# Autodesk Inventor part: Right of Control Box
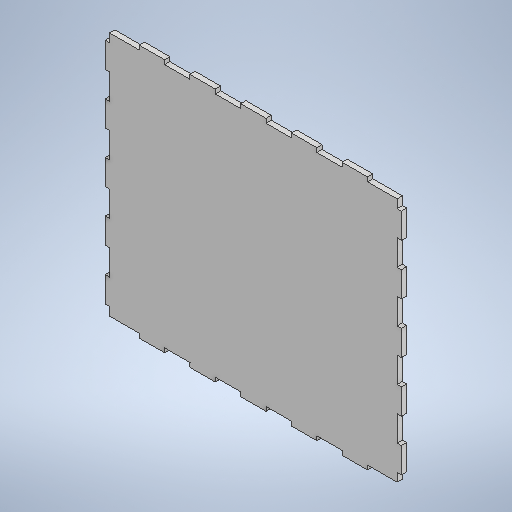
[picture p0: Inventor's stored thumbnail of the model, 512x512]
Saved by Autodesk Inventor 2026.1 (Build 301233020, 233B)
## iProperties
Created: 2026-11
Part Number: Right of Control Box
Material: Generic
Document SubType Name: Modeling
Designer: hp
Density: 1 g/cm^3
Appearance: Default
Author: hp
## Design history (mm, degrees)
sketch "Sketch1"
  geometry: L1 (104, 4)-(104, 0); L2 (104, 4)-(104, 0); L3 (104, 0)-(80, 0); L4 (80, 0)-(80, 4); L5 (104, 0)-(80, 0); L6 (80, 0)-(80, 4); L7 (80, 4)-(104, 4); L8 (80, 4)-(104, 4); L9 (128, 0)-(128, 4); L10 (128, 0)-(128, 4); L11 (152, 0)-(128, 0); L12 (128, 4)-(152, 4); L13 (152, 0)-(128, 0); L14 (128, 4)-(152, 4); L15 (152, 4)-(152, 0); L16 (0, 240)-(280, 240); L17 (280, 240)-(280, 0); L18 (280, 0)-(0, 0); L19 (0, 0)-(0, 240); L20 (56, 4)-(56, 0); L21 (56, 0)-(32, 0); L22 (32, 0)-(32, 4); L23 (32, 4)-(56, 4); L24 (140, 240)-(140, 0); L25 (280, 120)-(0, 120); L26 (176, 0)-(176, 4); L27 (176, 0)-(176, 4); L28 (200, 0)-(176, 0); L29 (200, 0)-(176, 0); L30 (176, 4)-(200, 4); L31 (200, 4)-(200, 0); L32 (224, 0)-(224, 4); L33 (248, 4)-(248, 0); L34 (224, 4)-(248, 4); L35 (248, 0)-(224, 0); L36 (152, 4)-(152, 0); L37 (128, 240)-(128, 236); L38 (128, 240)-(128, 236); L39 (128, 240)-(128, 236); L40 (128, 236)-(152, 236); L41 (128, 236)-(152, 236); L42 (152, 240)-(128, 240); L43 (152, 240)-(128, 240); L44 (152, 236)-(152, 240); L45 (152, 236)-(152, 240); L46 (200, 236)-(200, 240); L47 (176, 240)-(176, 236); L48 (176, 240)-(176, 236); L49 (200, 240)-(176, 240); L50 (176, 236)-(200, 236); L51 (200, 240)-(176, 240); L52 (176, 236)-(200, 236); L53 (200, 236)-(200, 240); L54 (224, 240)-(224, 236); L55 (224, 236)-(248, 236); L56 (248, 240)-(224, 240); L57 (248, 236)-(248, 240); L58 (176, 4)-(200, 4); L59 (200, 4)-(200, 0); L60 (152, 4)-(152, 0); L61 (128, 0)-(128, 4); L62 (152, 0)-(128, 0); L63 (128, 4)-(152, 4); L64 (80, 240)-(80, 236)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; 113 further points
  constraints: 308 end point, 90 symmetric about line, 8 parallel, 6 midpoint, 5 horizontal, 4 perpendicular, 2 vertical, 1 point on line, 3 other
  dimensions: "d14" = 280 distance of L17.end L18.end; "d15" = 240 distance of L16.end L17.end; "d16" = 24 distance of L9.end L12.end; "d17" = 4 distance of L9.start L9.end; "d18" = 48 distance of L11.start L1.end; "d19" = 48 distance of L11.start L28.start; "d20" = 4 distance of L97.end L96.end; "d21" = 24 distance of L96.end L95.end; "d22" = 48 distance of L95.end L83.end; "d23" = 48 distance of L95.end L107.end; "d24" = 4 distance between parallel lines of L16 L151
extrude "Extrusion2" new body sketch "Sketch1" distance "d25" = 5; taper "d26" = 0 deg
body "Solid2"
node "Sketch Rectangular Pattern2" dims "d18" = 48, "d19" = 48
node "Sketch Rectangular Pattern4" dims "d22" = 48, "d23" = 48
